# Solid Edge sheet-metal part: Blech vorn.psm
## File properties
Author: heha
Template: Normal.psm
Last saved by: heha
Revision: 14
Application: Solid Edge
Materialstärke: 1,50 mm
Biegeradius: 1,50 mm
Ausklinkungsbreite: 1,50 mm
Ausklinkungslänge: 1,50 mm
Neutralfaktor: 0,330
Dichte: 2,712 kg/dm^3
Genauigkeit: 0,990
Minimale Bogenlänge: 0,10 mm
Abweichungstoleranz: 0,10 mm
Material: Aluminium, 1060
Teilflächenformatvorlage: Aluminium
Füllformatvorlage: ANSI38(Aluminum)
Virtuelle Formatvorlage: Poliertes Aluminium
Coef. of Thermal Exp: 2.3e-05
Thermal Conductivity: 221.0
Specific Heat: 920.0
Modulus of Elasticity: 68947570000.0
Poission's Ratio: 0.33
Yield Stress: 27579028.0
Ultimate Stress: 68947570.0
Elongation: 0.0
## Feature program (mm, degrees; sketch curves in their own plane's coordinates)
base tab "unnamed BaseTab 1"
sheet metal cutout "unnamed SheetMetalCutout 1"
sheet metal cutout "unnamed SheetMetalCutout 2"
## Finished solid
Body 1: solid body, 30 faces, 76 edges, 40 vertices.
  Faces by surface: cylinder 18, plane 12
  Edges by curve: line 40, circle 36
Bounding box of the edges (mm): 123.000 x 1.500 x 76.000, from (-61.5, -1.5, -38) to (61.5, 0, 38).
Cylindrical faces by radius (mm): R1.6 x8, R2 x4, R6.4 x6
Planar faces by outward normal: +x 1, +y 1, +z 3, -x 1, -y 1, -z 5
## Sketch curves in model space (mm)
circle centre (-38.1, 0, -12.4) radius 6.4
circle centre (-12.7, 0, -12.4) radius 6.4
circle centre (38.1, 0, -12.4) radius 6.4
circle centre (12.7, 0, -12.4) radius 6.4
circle centre (38.1, 0, 12.4) radius 6.4
circle centre (12.7, 0, 12.4) radius 6.4
line (49.5, 0, 21.2) -> (49.5, 0, 19.4)
line (49.5, 0, 19.4) -> (-49.5, 0, 19.4)
line (-49.5, 0, 19.4) -> (-49.5, 0, 21.2)
line (-49.5, 0, 21.2) -> (49.5, 0, 21.2)
line (49.5, 0, -19.4) -> (49.5, 0, -21.2)
line (49.5, 0, -21.2) -> (-49.5, 0, -21.2)
line (-49.5, 0, -21.2) -> (-49.5, 0, -19.4)
line (-49.5, 0, -19.4) -> (49.5, 0, -19.4)
line (-45.4, 0, -6.9) -> (-30.8, 0, -6.9)
line (-30.8, 0, -6.9) -> (-30.8, 0, -19.4)
line (-30.8, 0, -19.4) -> (-45.4, 0, -19.4)
line (-45.4, 0, -19.4) -> (-45.4, 0, -6.9)
line (-20, 0, -6.9) -> (-5.4, 0, -6.9)
line (-5.4, 0, -6.9) -> (-5.4, 0, -19.4)
line (-5.4, 0, -19.4) -> (-20, 0, -19.4)
line (-20, 0, -19.4) -> (-20, 0, -6.9)
line (5.4, 0, -6.9) -> (20, 0, -6.9)
line (20, 0, -6.9) -> (20, 0, -19.4)
line (20, 0, -19.4) -> (5.4, 0, -19.4)
line (5.4, 0, -19.4) -> (5.4, 0, -6.9)
line (30.8, 0, -19.4) -> (45.4, 0, -19.4)
line (45.4, 0, -19.4) -> (45.4, 0, -6.9)
line (45.4, 0, -6.9) -> (30.8, 0, -6.9)
line (30.8, 0, -6.9) -> (30.8, 0, -19.4)
line (5.4, 0, 19.4) -> (20, 0, 19.4)
line (20, 0, 19.4) -> (20, 0, 6.9)
line (20, 0, 6.9) -> (5.4, 0, 6.9)
line (5.4, 0, 6.9) -> (5.4, 0, 19.4)
line (30.8, 0, 19.4) -> (45.4, 0, 19.4)
line (45.4, 0, 19.4) -> (45.4, 0, 6.9)
line (45.4, 0, 6.9) -> (30.8, 0, 6.9)
line (30.8, 0, 6.9) -> (30.8, 0, 19.4)
circle centre (-47.5, 0, -24) radius 1.3
line (-41.5, 0, -27) -> (0, 0, -27)
line (-41.5, 0, -25.2) -> (0, 0, -25.2)
line (-41.5, 0, -28) -> (-41.5, 0, -27)
line (-49.5, 0, -28) -> (-41.5, 0, -28)
arc centre (-49.5, 0, -26) radius 2 from (-51.5, 0, -26) through (-50.8725, 0, -27.4547) to (-49.5, 0, -28)
line (-51.5, 0, 26) -> (-51.5, 0, -26)
arc centre (-49.5, 0, 26) radius 2 from (-49.5, 0, 28) through (-50.9547, 0, 27.3725) to (-51.5, 0, 26)
line (-41.5, 0, 28) -> (-49.5, 0, 28)
line (-44.5, 0, -25.2) -> (-41.5, 0, -25.2)
line (-44.5, 0, -27) -> (-44.5, 0, -25.2)
line (-41.5, 0, -27) -> (-44.5, 0, -27)
line (-47.5, 0, 0.9) -> (-47.5, 0, 2)
line (-49.5, 0, 0.9) -> (-47.5, 0, 0.9)
line (-49.5, 0, -0.9) -> (-49.5, 0, 0.9)
line (-47.5, 0, -0.9) -> (-49.5, 0, -0.9)
line (-47.5, 0, -2) -> (-47.5, 0, -0.9)
line (-49.5, 0, -2) -> (-47.5, 0, -2)
line (-49.5, 0, -3.8) -> (-49.5, 0, -2)
line (-47.5, 0, -3.8) -> (-49.5, 0, -3.8)
line (-47.5, 0, -4.9) -> (-47.5, 0, -3.8)
line (-49.5, 0, -4.9) -> (-47.5, 0, -4.9)
line (-49.5, 0, -6.7) -> (-49.5, 0, -4.9)
line (-47.5, 0, -6.7) -> (-49.5, 0, -6.7)
line (-47.5, 0, -7.8) -> (-47.5, 0, -6.7)
line (-49.5, 0, -7.8) -> (-47.5, 0, -7.8)
line (-49.5, 0, -9.6) -> (-49.5, 0, -7.8)
line (-47.5, 0, -9.6) -> (-49.5, 0, -9.6)
line (-47.5, 0, -10.7) -> (-47.5, 0, -9.6)
line (-49.5, 0, -10.7) -> (-47.5, 0, -10.7)
line (-49.5, 0, -12.5) -> (-49.5, 0, -10.7)
line (-47.5, 0, -12.5) -> (-49.5, 0, -12.5)
line (-47.5, 0, -13.6) -> (-47.5, 0, -12.5)
line (-49.5, 0, -13.6) -> (-47.5, 0, -13.6)
line (-49.5, 0, -15.4) -> (-49.5, 0, -13.6)
line (-47.5, 0, -15.4) -> (-49.5, 0, -15.4)
line (-47.5, 0, -16.5) -> (-47.5, 0, -15.4)
line (-49.5, 0, -16.5) -> (-47.5, 0, -16.5)
line (-49.5, 0, -18.3) -> (-49.5, 0, -16.5)
line (-47.5, 0, -18.3) -> (-49.5, 0, -18.3)
line (-47.5, 0, -19.4) -> (-47.5, 0, -18.3)
line (-49.5, 0, -19.4) -> (-47.5, 0, -19.4)
line (-49.5, 0, -21.2) -> (-49.5, 0, -19.4)
line (-46.9, 0, -21.2) -> (-49.5, 0, -21.2)
line (-46.9, 0, -22.8) -> (-46.9, 0, -21.2)
line (-41.5, 0, -22.8) -> (-46.9, 0, -22.8)
line (-41.5, 0, -25.2) -> (-41.5, 0, -22.8)
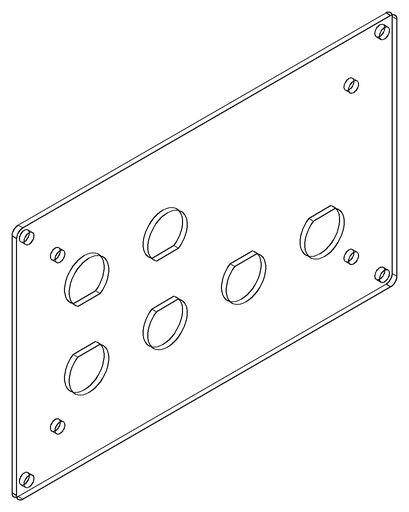
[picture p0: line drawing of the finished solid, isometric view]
